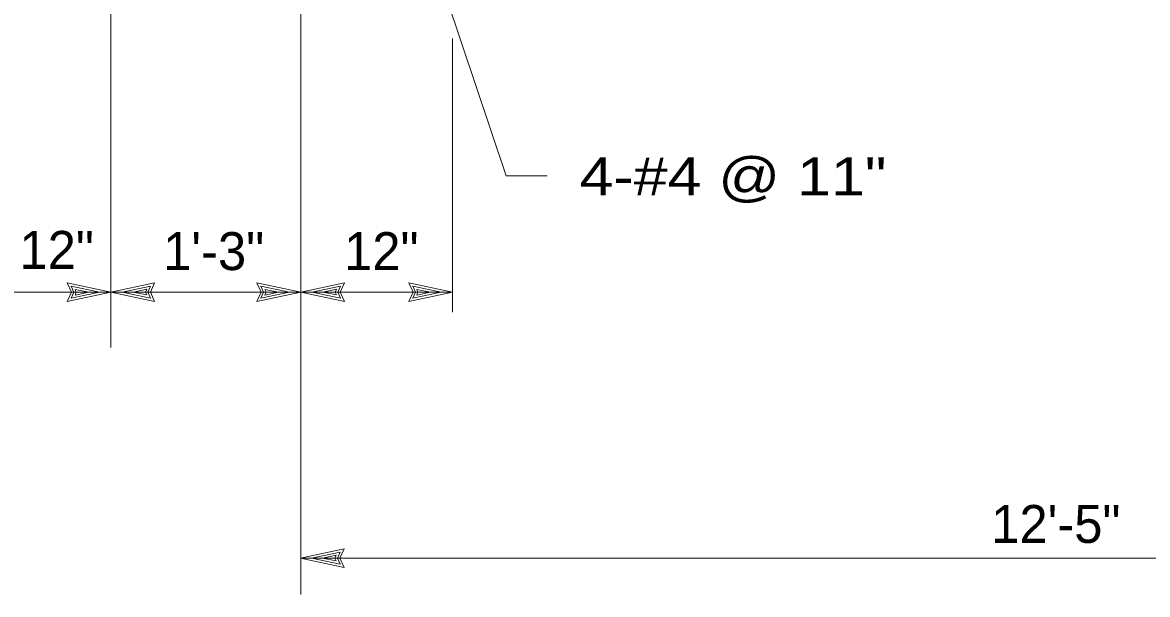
# Model space of a CAD drawing. Extents: x -24.3 to 17.7, y -17.6 to 12.4.
# Drawn here: x -16.992 to -13.287, y -14.496 to -12.611 of the extents above; entities that cross this region are included whole.
import ezdxf
from ezdxf.enums import TextEntityAlignment as Align

# ---------------------------------------------------------------- set-up
doc = ezdxf.new("R2010")
doc.units = 0
doc.header["$LTSCALE"] = 0.05
doc.layers.add('1', color=7, linetype='Continuous', lineweight=13)

msp = doc.modelspace()

# ---------------------------------------------------------------- linework, layer by layer
at = {"layer": '1'}
for p, q in [((-16.70069, -13.6816), (-16.70069, -12.0626)), ((-16.07569, -14.4956), (-16.07569, -12.0536)), ((-15.39869, -13.1156), (-15.62969, -12.4286)), ((-15.57569, -13.5656), (-15.57569, -12.6636)), ((-15.39869, -13.1156), (-15.26369, -13.1156)), ((-16.70069, -13.4996), (-16.84469, -13.4686)), ((-16.73769, -13.4996), (-16.83169, -13.4796)), ((-16.82269, -13.4996), (-16.83169, -13.4796)), ((-16.70069, -13.4996), (-16.55669, -13.4686)), ((-16.66369, -13.4996), (-16.56969, -13.4796)), ((-16.56969, -13.4796), (-16.57869, -13.4996)), ((-16.07569, -13.4996), (-16.21969, -13.4686)), ((-16.11269, -13.4996), (-16.20669, -13.4796)), ((-16.19769, -13.4996), (-16.20669, -13.4796)), ((-16.07569, -13.4996), (-15.93169, -13.4686)), ((-16.03869, -13.4996), (-15.94469, -13.4796)), ((-15.94469, -13.4796), (-15.95369, -13.4996)), ((-15.57569, -13.4996), (-15.71969, -13.4686)), ((-15.61269, -13.4996), (-15.70669, -13.4796)), ((-15.69769, -13.4996), (-15.70669, -13.4796)), ((-16.70069, -13.4996), (-16.84469, -13.5306)), ((-16.73769, -13.4996), (-16.83169, -13.5196)), ((-16.83169, -13.5196), (-16.82269, -13.4996)), ((-16.77369, -13.4996), (-16.81869, -13.4906)), ((-16.81469, -13.4996), (-16.81869, -13.4906)), ((-16.77369, -13.4996), (-16.81869, -13.5096)), ((-16.81869, -13.5096), (-16.81469, -13.4996)), ((-16.70069, -13.4996), (-16.55669, -13.5306)), ((-16.66369, -13.4996), (-16.56969, -13.5196)), ((-16.62769, -13.4996), (-16.58269, -13.4896)), ((-16.62769, -13.4996), (-16.58269, -13.5086)), ((-16.58269, -13.4896), (-16.58669, -13.4996)), ((-16.58669, -13.4996), (-16.58269, -13.5086)), ((-16.57869, -13.4996), (-16.56969, -13.5196)), ((-16.07569, -13.4996), (-16.21969, -13.5306)), ((-16.11269, -13.4996), (-16.20669, -13.5196)), ((-16.20669, -13.5196), (-16.19769, -13.4996)), ((-16.14869, -13.4996), (-16.19369, -13.4906)), ((-16.18969, -13.4996), (-16.19369, -13.4906)), ((-16.14869, -13.4996), (-16.19369, -13.5096)), ((-16.19369, -13.5096), (-16.18969, -13.4996)), ((-16.07569, -13.4996), (-15.57569, -13.4996)), ((-16.07569, -13.4996), (-15.93169, -13.5306)), ((-16.03869, -13.4996), (-15.94469, -13.5196)), ((-16.00269, -13.4996), (-15.95769, -13.4896)), ((-16.00269, -13.4996), (-15.95769, -13.5086)), ((-15.95769, -13.4896), (-15.96169, -13.4996)), ((-15.96169, -13.4996), (-15.95769, -13.5086)), ((-15.95369, -13.4996), (-15.94469, -13.5196)), ((-15.57569, -13.4996), (-15.71969, -13.5306)), ((-15.61269, -13.4996), (-15.70669, -13.5196)), ((-15.70669, -13.5196), (-15.69769, -13.4996)), ((-15.64869, -13.4996), (-15.69369, -13.4906)), ((-15.68969, -13.4996), (-15.69369, -13.4906)), ((-15.64869, -13.4996), (-15.69369, -13.5096)), ((-15.69369, -13.5096), (-15.68969, -13.4996)), ((-16.07669, -14.3756), (-15.93269, -14.3446)), ((-16.03969, -14.3756), (-15.94569, -14.3556)), ((-16.00369, -14.3756), (-15.95869, -14.3656)), ((-15.95869, -14.3656), (-15.96269, -14.3756)), ((-15.94569, -14.3556), (-15.95469, -14.3756)), ((-16.07669, -14.3756), (-15.93269, -14.4066)), ((-16.03969, -14.3756), (-15.94569, -14.3956)), ((-16.00369, -14.3756), (-15.95869, -14.3846)), ((-15.96269, -14.3756), (-15.95869, -14.3846)), ((-15.95469, -14.3756), (-15.94569, -14.3956))]:
    msp.add_line(p, q, dxfattribs=at)
for points in [[(-16.84469, -13.5306), (-16.83069, -13.4996), (-16.84469, -13.4686)], [(-16.55669, -13.4686), (-16.57069, -13.4996), (-16.55669, -13.5306)], [(-16.21969, -13.5306), (-16.20569, -13.4996), (-16.21969, -13.4686)], [(-15.93169, -13.4686), (-15.94569, -13.4996), (-15.93169, -13.5306)], [(-15.71969, -13.5306), (-15.70569, -13.4996), (-15.71969, -13.4686)], [(-17.20069, -13.4996), (-16.70069, -13.4996), (-16.07569, -13.4996)], [(-15.93269, -14.3446), (-15.94669, -14.3756), (-15.93269, -14.4066)], [(-16.07669, -14.3756), (-9.90869, -14.3756), (-3.74269, -14.3756)]]:
    msp.add_lwpolyline(points, dxfattribs=at)

# ---------------------------------------------------------------- texts
at = {"layer": '1', "width": 1.2}
msp.add_text('4-#4 @ 11"', height=0.125, dxfattribs=at).set_placement((-15.15769, -13.1806))
at = {"layer": '1'}
for s, p in [('12"', (-16.87919, -13.4226)), ('1\'-3"', (-16.36219, -13.4266)), ('12"', (-15.81019, -13.4266)), ('12\'-5"', (-13.58917, -14.3257))]:
    msp.add_text(s, height=0.125, dxfattribs=at).set_placement(p, align=Align.CENTER)

doc.saveas('drawing.dxf')
